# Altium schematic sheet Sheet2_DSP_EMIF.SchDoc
size A3
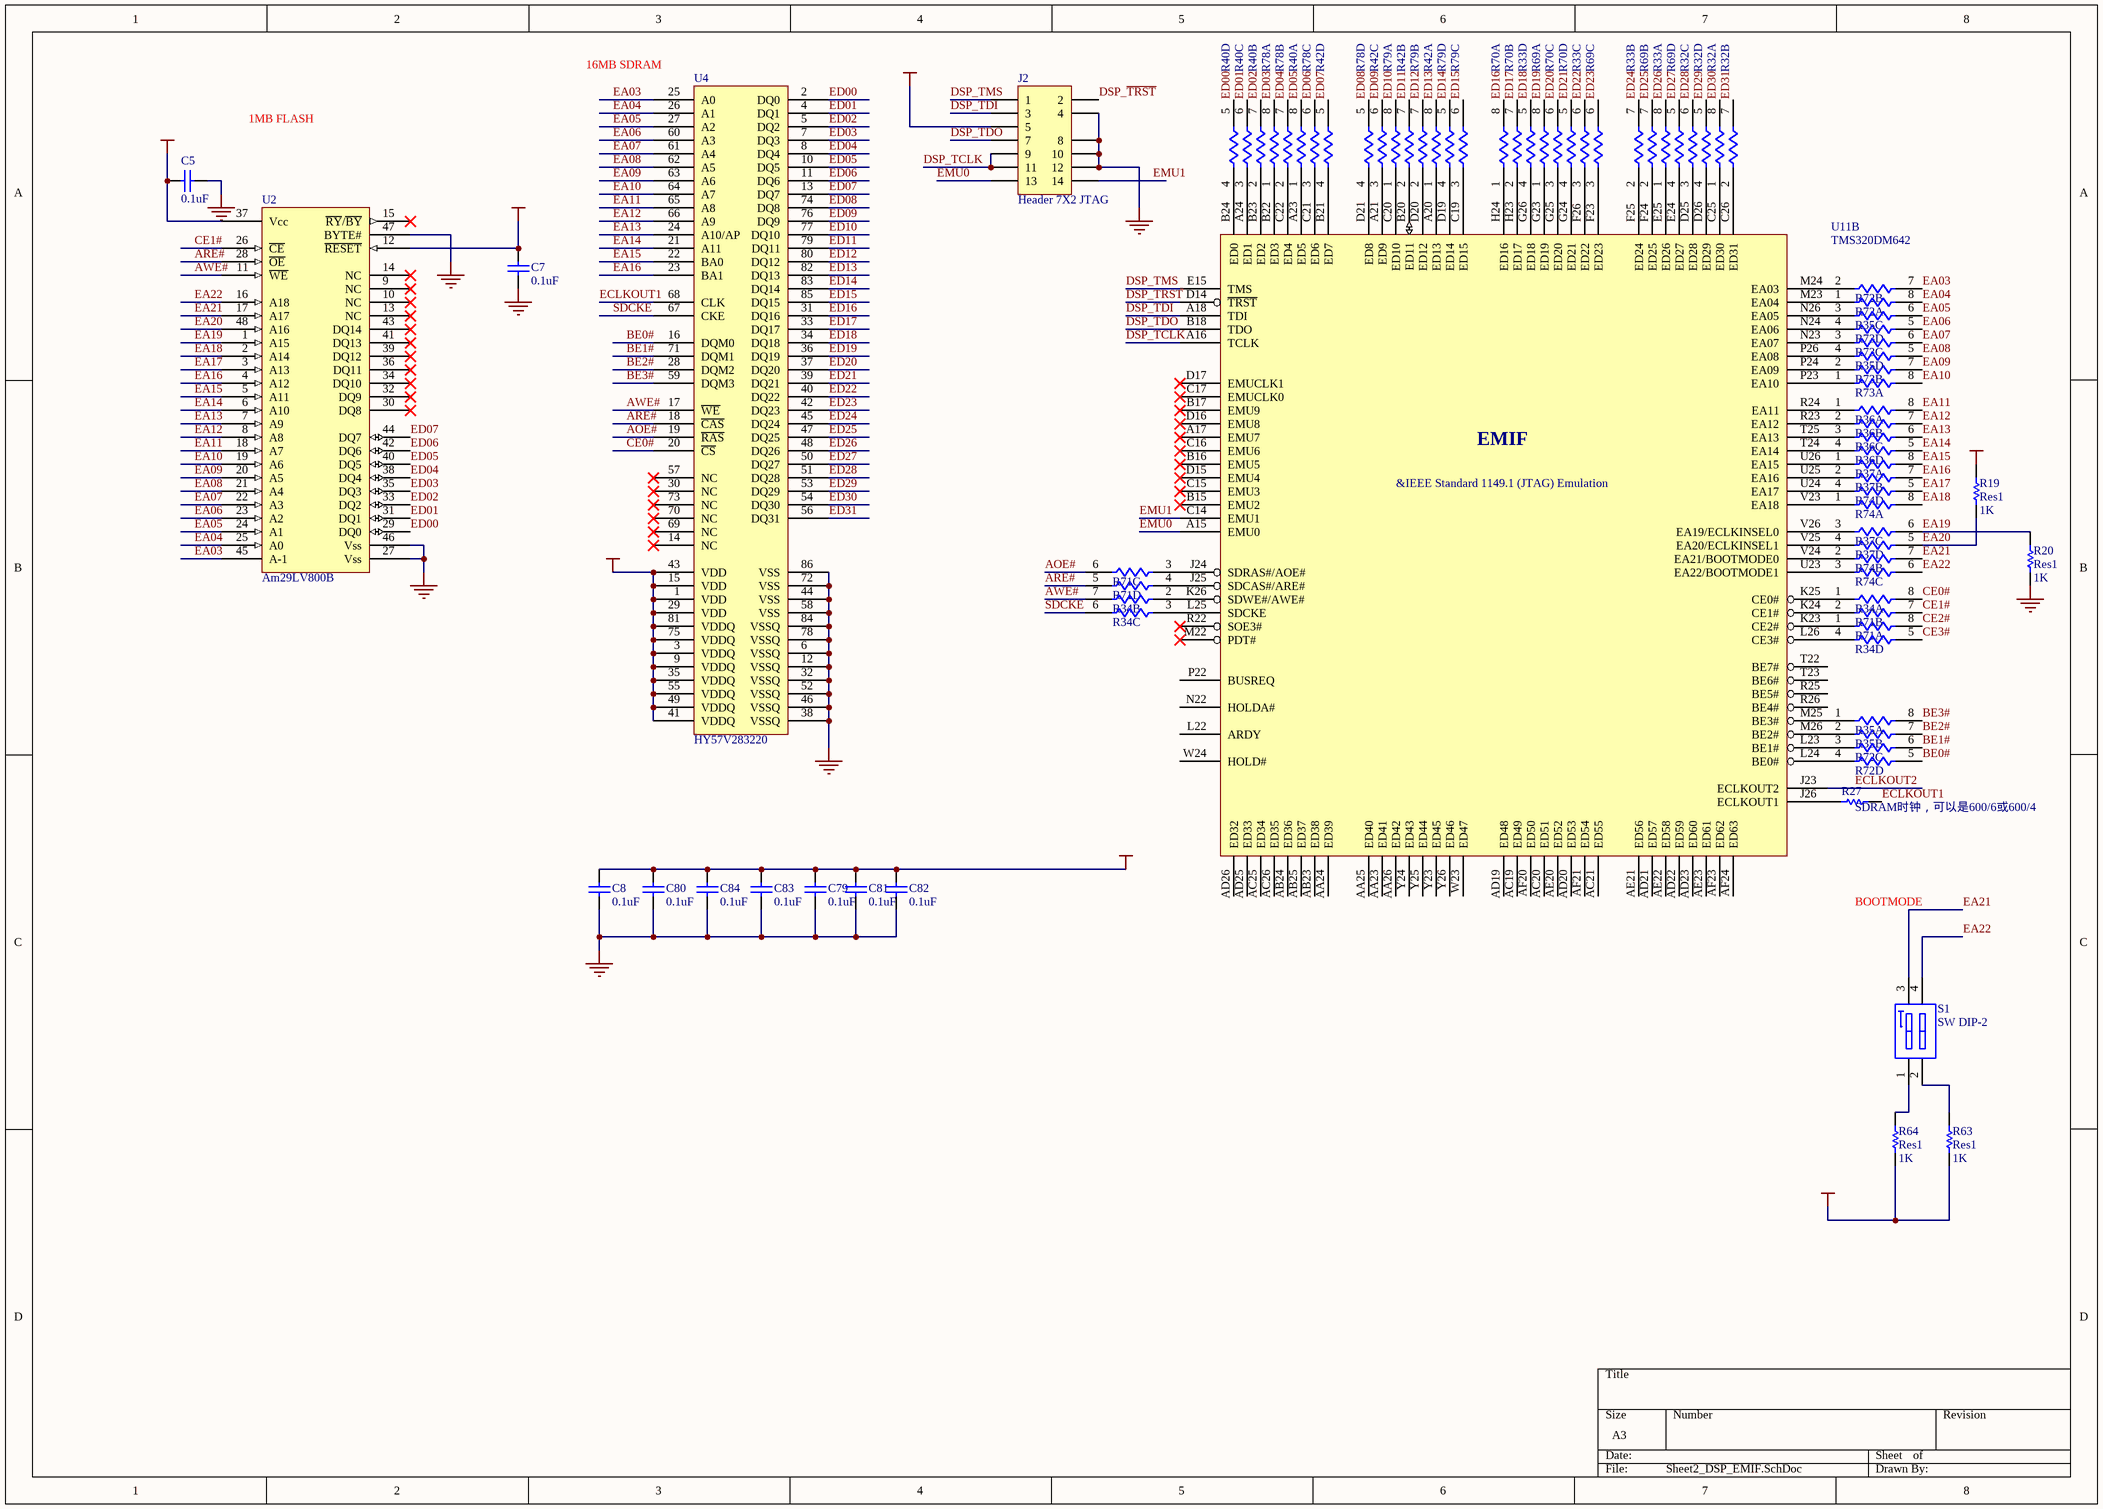
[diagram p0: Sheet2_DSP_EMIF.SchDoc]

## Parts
C5  value 0.1uF  [C1608-0603]  (hidden comment: Cap)
C7  value 0.1uF  [C1608-0603]  (hidden comment: Cap)
C8  value 0.1uF  [C1608-0603]  (hidden comment: Cap)
C79  value 0.1uF  [C1608-0603]  (hidden comment: Cap)
C80  value 0.1uF  [C1608-0603]  (hidden comment: Cap)
C81  value 0.1uF  [C1608-0603]  (hidden comment: Cap)
C82  value 0.1uF  [C1608-0603]  (hidden comment: Cap)
C83  value 0.1uF  [C1608-0603]  (hidden comment: Cap)
C84  value 0.1uF  [C1608-0603]  (hidden comment: Cap)
J2  Header 7X2 JTAG  [HDR2X7]
R19  Res1  value 1K  [CR1608-0603]
R20  Res1  value 1K  [CR1608-0603]
R27  Res1  [CR1608-0603]  (value not drawn)
R32  R0604_4  [R0603_4]  (value not drawn)  (parts A,B,C,D of 4)
R33  R0604_4  [R0603_4]  (value not drawn)  (parts A,B,C,D of 4)
R34  R0604_4  [R0603_4]  (value not drawn)  (parts A,B,C,D of 4)
R35  R0604_4  [R0603_4]  (value not drawn)  (parts A,B,C,D of 4)
R36  R0604_4  [R0603_4]  (value not drawn)  (parts A,B,C,D of 4)
R37  R0604_4  [R0603_4]  (value not drawn)  (parts A,B,C,D of 4)
R40  R0604_4  [R0603_4]  (value not drawn)  (parts A,B,C,D of 4)
R42  R0604_4  [R0603_4]  (value not drawn)  (parts A,B,C,D of 4)
R63  Res1  value 1K  [CR1608-0603]
R64  Res1  value 1K  [CR1608-0603]
R69  R0604_4  [R0603_4]  (value not drawn)  (parts A,B,C,D of 4)
R70  R0604_4  [R0603_4]  (value not drawn)  (parts A,B,C,D of 4)
R71  R0604_4  [R0603_4]  (value not drawn)  (parts A,B,C,D of 4)
R72  R0604_4  [R0603_4]  (value not drawn)  (parts A,B,C,D of 4)
R73  R0604_4  [R0603_4]  (value not drawn)  (parts A,B,C,D of 4)
R74  R0604_4  [R0603_4]  (value not drawn)  (parts A,B,C,D of 4)
R78  R0604_4  [R0603_4]  (value not drawn)  (parts A,B,C,D of 4)
R79  R0604_4  [R0603_4]  (value not drawn)  (parts A,B,C,D of 4)
S1  SW DIP-2  [HEADER2X2]
U2  Am29LV800B  [TSOP48]
U4  HY57V283220  [TSOP86]
U11  TMS320DM642  [GNZ548]  (part B of 5)

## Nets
GND: C5.1 C7.2 C8.1 C79.1 C80.1 C81.1 C82.1 C83.1 C84.1 J2.4 J2.8 J2.10 J2.12 R20.1 U2.27(Vss) U2.46(Vss) U2.47(BYTE#) U4.6(VSSQ) U4.12(VSSQ) U4.32(VSSQ) U4.38(VSSQ) U4.44(VSS) U4.46(VSSQ) U4.52(VSSQ) U4.58(VSS) U4.72(VSS) U4.78(VSSQ) U4.84(VSSQ) U4.86(VSS)
V3.3: C5.2 C7.1 C8.2 C79.2 C80.2 C81.2 C82.2 C83.2 C84.2 J2.5 R19.2 R63.1 R64.1 U2.12(~{RESET}) U2.37(Vcc) U4.1(VDD) U4.3(VDDQ) U4.9(VDDQ) U4.15(VDD) U4.29(VDD) U4.35(VDDQ) U4.41(VDDQ) U4.43(VDD) U4.49(VDDQ) U4.55(VDDQ) U4.75(VDDQ) U4.81(VDDQ)
AOE#: R71.6 U4.19(~{RAS})
ARE#: R71.5 U2.28(~{OE}) U4.18(~{CAS})
AWE#: R34.7 U2.11(~{WE}) U4.17(~{WE})
BE0#: R72.5 U4.16(DQM0)
BE1#: R72.6 U4.71(DQM1)
BE2#: R35.7 U4.28(DQM2)
BE3#: R35.8 U4.59(DQM3)
CE0#: R34.8 U4.20(~{CS})
CE1#: R71.7 U2.26(~{CE})
CE2#: R71.8
CE3#: R34.5
DSP_~{TRST}: J2.2 U11.D14(~{TRST})
DSP_TCLK: J2.9 J2.11 U11.A16(TCLK)
DSP_TDI: J2.3 U11.A18(TDI)
DSP_TDO: J2.7 U11.B18(TDO)
DSP_TMS: J2.1 U11.E15(TMS)
EA03: R72.7 U2.45(A-1) U4.25(A0)
EA04: R72.8 U2.25(A0) U4.26(A1)
EA05: R35.6 U2.24(A1) U4.27(A2)
EA06: R73.5 U2.23(A2) U4.60(A3)
EA07: R73.6 U2.22(A3) U4.61(A4)
EA08: R35.5 U2.21(A4) U4.62(A5)
EA09: R73.7 U2.20(A5) U4.63(A6)
EA10: R73.8 U2.19(A6) U4.64(A7)
EA11: R36.8 U2.18(A7) U4.65(A8)
EA12: R36.7 U2.8(A8) U4.66(A9)
EA13: R36.6 U2.7(A9) U4.24(A10/AP)
EA14: R36.5 U2.6(A10) U4.21(A11)
EA15: R37.8 U2.5(A11) U4.22(BA0)
EA16: R37.7 U2.4(A12) U4.23(BA1)
EA17: R74.5 U2.3(A13)
EA18: R74.8 U2.2(A14)
EA19: R20.2 R37.6 U2.1(A15)
EA20: R19.1 R37.5 U2.48(A16)
EA21: R74.7 S1.3(B1) U2.17(A17)
EA22: R74.6 S1.4(B2) U2.16(A18)
ECLKOUT1: R27.2 U4.68(CLK)
ECLKOUT2: U11.J23(ECLKOUT2)
ED00: R40.5 U2.29(DQ0) U4.2(DQ0)
ED01: R40.6 U2.31(DQ1) U4.4(DQ1)
ED02: R40.7 U2.33(DQ2) U4.5(DQ2)
ED03: R78.8 U2.35(DQ3) U4.7(DQ3)
ED04: R78.7 U2.38(DQ4) U4.8(DQ4)
ED05: R40.8 U2.40(DQ5) U4.10(DQ5)
ED06: R78.6 U2.42(DQ6) U4.11(DQ6)
ED07: R42.5 U2.44(DQ7) U4.13(DQ7)
ED08: R78.5 U4.74(DQ8)
ED09: R42.6 U4.76(DQ9)
ED10: R79.8 U4.77(DQ10)
ED11: R42.7 U4.79(DQ11)
ED12: R79.7 U4.80(DQ12)
ED13: R42.8 U4.82(DQ13)
ED14: R79.5 U4.83(DQ14)
ED15: R79.6 U4.85(DQ15)
ED16: R70.8 U4.31(DQ16)
ED17: R70.7 U4.33(DQ17)
ED18: R33.5 U4.34(DQ18)
ED19: R69.8 U4.36(DQ19)
ED20: R70.6 U4.37(DQ20)
ED21: R70.5 U4.39(DQ21)
ED22: R33.6 U4.40(DQ22)
ED23: R69.6 U4.42(DQ23)
ED24: R33.7 U4.45(DQ24)
ED25: R69.7 U4.47(DQ25)
ED26: R33.8 U4.48(DQ26)
ED27: R69.5 U4.50(DQ27)
ED28: R32.6 U4.51(DQ28)
ED29: R32.5 U4.53(DQ29)
ED30: R32.8 U4.54(DQ30)
ED31: R32.7 U4.56(DQ31)
EMU0: J2.13 U11.A15(EMU0)
EMU1: J2.14 U11.C14(EMU1)
SDCKE: R34.6 U4.67(CKE)
NetR27_1: R27.1 U11.J26(ECLKOUT1)
NetR32_1: R32.1 U11.C25(ED30)
NetR32_2: R32.2 U11.C26(ED31)
NetR32_3: R32.3 U11.D25(ED28)
NetR32_4: R32.4 U11.D26(ED29)
NetR33_1: R33.1 U11.E25(ED26)
NetR33_2: R33.2 U11.F25(ED24)
NetR33_3: R33.3 U11.F26(ED22)
NetR33_4: R33.4 U11.G26(ED18)
NetR34_1: R34.1 U11.K25(CE0#)
NetR34_2: R34.2 U11.K26(SDWE#/AWE#)
NetR34_3: R34.3 U11.L25(SDCKE)
NetR34_4: R34.4 U11.L26(CE3#)
NetR35_1: R35.1 U11.M25(BE3#)
NetR35_2: R35.2 U11.M26(BE2#)
NetR35_3: R35.3 U11.N26(EA05)
NetR35_4: R35.4 U11.P26(EA08)
NetR36_1: R36.1 U11.R24(EA11)
NetR36_2: R36.2 U11.R23(EA12)
NetR36_3: R36.3 U11.T25(EA13)
NetR36_4: R36.4 U11.T24(EA14)
NetR37_1: R37.1 U11.U26(EA15)
NetR37_2: R37.2 U11.U25(EA16)
NetR37_3: R37.3 U11.V26(EA19/ECLKINSEL0)
NetR37_4: R37.4 U11.V25(EA20/ECLKINSEL1)
NetR40_1: R40.1 U11.A23(ED5)
NetR40_2: R40.2 U11.B23(ED2)
NetR40_3: R40.3 U11.A24(ED1)
NetR40_4: R40.4 U11.B24(ED0)
NetR42_1: R42.1 U11.A20(ED13)
NetR42_2: R42.2 U11.B20(ED11)
NetR42_3: R42.3 U11.A21(ED9)
NetR42_4: R42.4 U11.B21(ED7)
NetR63_2: R63.2 S1.2(A2)
NetR64_2: R64.2 S1.1(A1)
NetR69_1: R69.1 U11.G23(ED19)
NetR69_2: R69.2 U11.F24(ED25)
NetR69_3: R69.3 U11.F23(ED23)
NetR69_4: R69.4 U11.E24(ED27)
NetR70_1: R70.1 U11.H24(ED16)
NetR70_2: R70.2 U11.H23(ED17)
NetR70_3: R70.3 U11.G25(ED20)
NetR70_4: R70.4 U11.G24(ED21)
NetR71_1: R71.1 U11.K23(CE2#)
NetR71_2: R71.2 U11.K24(CE1#)
NetR71_3: R71.3 U11.J24(SDRAS#/AOE#)
NetR71_4: R71.4 U11.J25(SDCAS#/ARE#)
NetR72_1: R72.1 U11.M23(EA04)
NetR72_2: R72.2 U11.M24(EA03)
NetR72_3: R72.3 U11.L23(BE1#)
NetR72_4: R72.4 U11.L24(BE0#)
NetR73_1: R73.1 U11.P23(EA10)
NetR73_2: R73.2 U11.P24(EA09)
NetR73_3: R73.3 U11.N23(EA07)
NetR73_4: R73.4 U11.N24(EA06)
NetR74_1: R74.1 U11.V23(EA18)
NetR74_2: R74.2 U11.V24(EA21/BOOTMODE0)
NetR74_3: R74.3 U11.U23(EA22/BOOTMODE1)
NetR74_4: R74.4 U11.U24(EA17)
NetR78_1: R78.1 U11.B22(ED3)
NetR78_2: R78.2 U11.C22(ED4)
NetR78_3: R78.3 U11.C21(ED6)
NetR78_4: R78.4 U11.D21(ED8)
NetR79_1: R79.1 U11.C20(ED10)
NetR79_2: R79.2 U11.D20(ED12)
NetR79_3: R79.3 U11.C19(ED15)
NetR79_4: R79.4 U11.D19(ED14)

Not connected (* = marked no-connect by the designer): J2 6; U2 9(NC)* 10(NC)* 13(NC)* 14(NC)* 15(~{RY}/~{BY})* 30(DQ8)* 32(DQ9)* 34(DQ10)* 36(DQ11)* 39(DQ12)* 41(DQ13)* 43(DQ14)*; U4 14(NC)* 30(NC)* 57(NC)* 69(NC)* 70(NC)* 73(NC)*; U11 A17(EMU7)* AA23(ED41) AA24(ED39) AA25(ED40) AA26(ED42) AB23(ED38) AB24(ED36) AB25(ED37) AC19(ED49) AC20(ED51) AC21(ED55) AC25(ED34) AC26(ED35) AD19(ED48) AD20(ED53) AD21(ED57) AD22(ED59) AD23(ED60) AD25(ED33) AD26(ED32) AE20(ED52) AE21(ED56) AE22(ED58) AE23(ED61) AF20(ED50) AF21(ED54) AF23(ED62) AF24(ED63) B15(EMU2)* B16(EMU5)* B17(EMU9)* C15(EMU3)* C16(EMU6)* C17(EMUCLK0)* D15(EMU4)* D16(EMU8)* D17(EMUCLK1)* L22(ARDY) M22(PDT#)* N22(HOLDA#) P22(BUSREQ) R22(SOE3#)* R25(BE5#) R26(BE4#) T22(BE7#) T23(BE6#) W23(ED47) W24(HOLD#) Y23(ED45) Y24(ED43) Y25(ED44) Y26(ED46)

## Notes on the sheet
- 16MB SDRAM
- 1MB FLASH
- (near R27) SDRAM时钟，可以是600/6或600/4
- BOOTMODE

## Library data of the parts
C5 C7 C8 C79-C84 = Cap: Capacitor
J2 = Header 7X2: Header, 7-Pin, Dual row
R19 R20 R63 R64 = Res1: Resistor
R27 = Res1: Resistor; Value: 33
R32-R37 R40 R42 R69-R74 R78 R79 = R0604_4: Resistor Array - Parts; Code - JEDEC: MS-012-AC; Code - IPC: SO16; Value: 33
S1 = SW DIP-2: DIP Switch
U4 = HY57V283220: by TX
